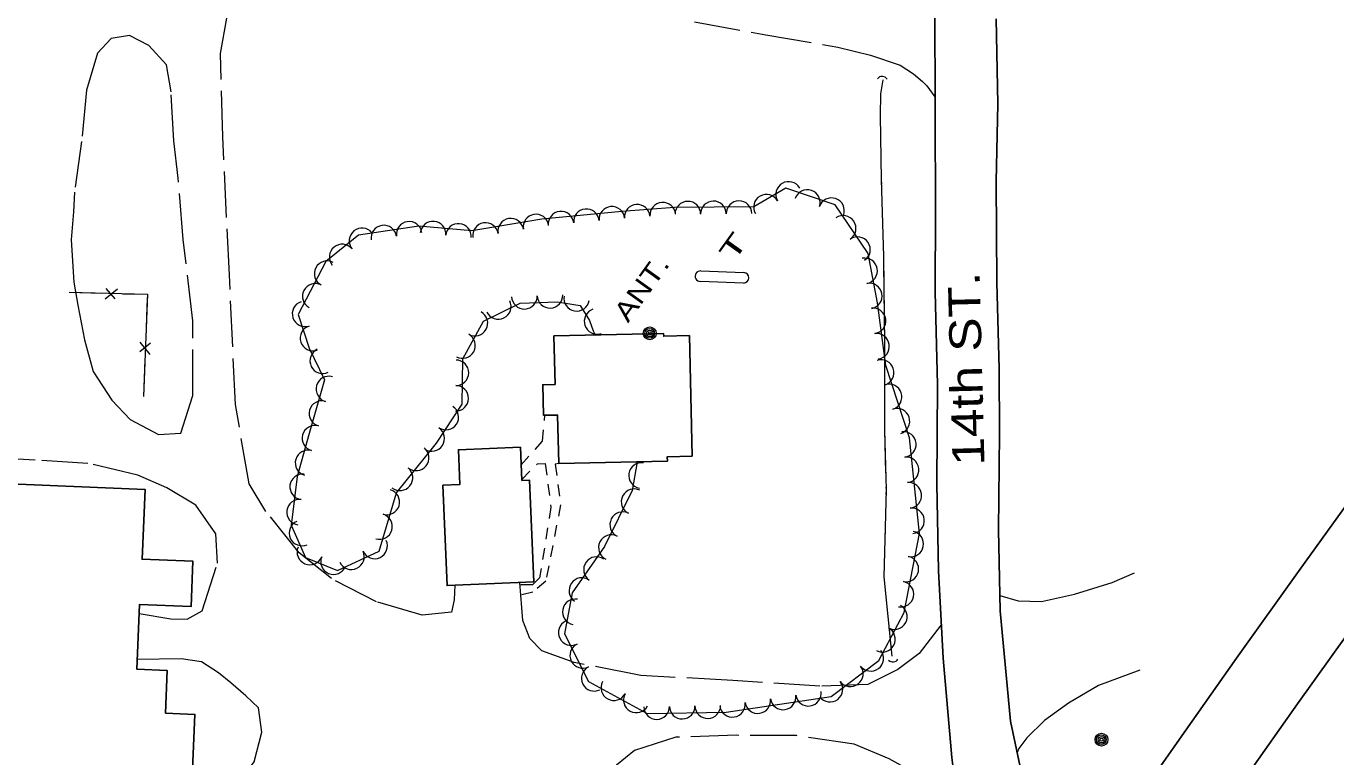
# Model space of a CAD drawing. Extents: x 299311 to 301657, y 49513 to 51866.
# Drawn here: x 300099.8 to 300509.3, y 50383.5 to 50612.1 of the extents above; entities that cross this region are included whole.
import ezdxf

# ---------------------------------------------------------------- set-up
doc = ezdxf.new("R2010")
doc.units = 0
doc.header["$LTSCALE"] = 2.4
doc.linetypes.add('LONG_DASHED', pattern=[7.5, 6, -1.5])
doc.linetypes.add('SHORT_DASHED', pattern=[2.7, 1.5, -1.2])
for name, color, linetype, lineweight in [('11', 7, 'Continuous', 25), ('12', 7, 'Continuous', 25), ('14', 7, 'Continuous', 13), ('15', 7, 'Continuous', 13), ('17', 7, 'LONG_DASHED', 13), ('18', 7, 'Continuous', 13), ('19', 7, 'Continuous', 13)]:
    doc.layers.add(name, color=color, linetype=linetype, lineweight=lineweight)

msp = doc.modelspace()

# ---------------------------------------------------------------- linework, layer by layer
at = {"layer": '11'}
for points in [[(300449.171, 50372.95), (300462.402, 50391.823), (300478.238, 50414.348), (300497.847, 50441.838), (300516.893, 50468.271), (300538.883, 50498.768), (300558.362, 50525.367), (300577.633, 50552.405), (300598.2, 50580.809), (300618.37, 50608.824), (300640.297, 50638.797)], [(300287.176, 50107.164), (300311.291, 50140.598), (300331.977, 50169.98), (300349.427, 50194.729), (300366.089, 50218.225), (300384.892, 50244.576), (300409.609, 50278.747), (300427.494, 50303.203), (300456.56, 50343.148), (300479.329, 50374.693), (300497.325, 50400.091), (300518.311, 50429.548), (300539.854, 50459.658), (300560.519, 50488.121), (300581.893, 50517.65), (300601.128, 50544.137), (300623.029, 50574.5), (300642.077, 50601.015), (300659.645, 50625.084)], [(300269.259, 50122.088), (300283.213, 50142.149), (300299.569, 50164.511), (300317.787, 50189.652), (300334.031, 50212.576), (300349.003, 50233.575), (300364.401, 50254.769), (300378.702, 50274.374), (300384.509, 50284.011), (300388.686, 50295.607), (300391.506, 50308.722), (300393.874, 50322.709), (300394.896, 50338.981), (300392.037, 50360.801), (300389.239, 50383.352), (300386.478, 50414.413), (300385.011, 50441.691), (300384.56, 50468.923), (300384.731, 50500.04), (300383.99, 50528.88), (300384.149, 50554.459), (300383.961, 50584.641), (300383.895, 50619.722)], [(300449.171, 50372.95), (300442.828, 50363.946), (300438.55, 50359.732), (300433.231, 50358.033), (300428.416, 50357.856), (300424.537, 50358.691), (300421.532, 50360.789), (300417.686, 50364.881), (300414.413, 50370.655), (300410.92, 50378.945), (300407.555, 50394.652), (300404.294, 50429.226), (300403.819, 50454.543), (300404.115, 50484.571), (300403.976, 50504.923), (300403.289, 50531.909), (300403.127, 50563.445), (300403.577, 50587.789), (300403.079, 50614.351)]]:
    msp.add_lwpolyline(points, dxfattribs=at)
at = {"layer": '12', "lineweight": 13}
for p, q in [((300324.092, 50531.73), (300310.602, 50532.209)), ((300310.717, 50535.507), (300324.21, 50535.029))]:
    msp.add_line(p, q, dxfattribs=at)
at = {"layer": '12'}
for points in [[(300266.299, 50475.267), (300300.277, 50476.021), (300300.246, 50477.416), (300308.024, 50477.589), (300307.188, 50515.281), (300299.121, 50515.102), (300299.102, 50515.943), (300264.806, 50515.181), (300265.142, 50500.013), (300261.333, 50499.929), (300261.545, 50490.353), (300265.962, 50490.451)], [(300258.474, 50438.236), (300257.154, 50470.104), (300254.774, 50470.005), (300254.344, 50480.389), (300234.944, 50479.585), (300235.394, 50468.713), (300230.076, 50468.493), (300231.375, 50437.114)], [(300075.204, 50355.583), (300150.684, 50352.453), (300152.523, 50396.811), (300143.36, 50397.191), (300143.912, 50410.516), (300134.414, 50410.91), (300135.256, 50431.215), (300151.36, 50430.548), (300151.947, 50444.691), (300136.039, 50445.35), (300136.945, 50467.2), (300079.901, 50469.565), (300077.032, 50400.381), (300077.062, 50400.38)]]:
    msp.add_lwpolyline(points, close=True, dxfattribs=at)
at = {"layer": '12', "lineweight": 13}
for centre, start, end in [((300310.603, 50533.86), 85.99939, 269.95747), ((300324.089, 50533.383), 270.09132, 85.83083)]:
    msp.add_arc(centre, 1.651, start, end, dxfattribs=at)
at = {"layer": '14'}
for centre, radius in [((300294.766, 50515.983), 2.018), ((300294.754, 50515.988), 1.518), ((300294.79, 50515.97), 1.008), ((300294.784, 50515.979), 0.502), ((300436.01, 50388.899), 2.018), ((300435.998, 50388.904), 1.518), ((300436.034, 50388.886), 1.008), ((300436.028, 50388.895), 0.502)]:
    msp.add_circle(centre, radius, dxfattribs=at)
at = {"layer": '15'}
for p, q in [((300113.25, 50528.829), (300123.34, 50528.571)), ((300124.47, 50526.779), (300128.32, 50529.965)), ((300124.726, 50530.057), (300127.477, 50526.771)), ((300137.551, 50524.42), (300137.169, 50514.334)), ((300138.637, 50512.929), (300135.318, 50510.219)), ((300135.363, 50513.226), (300138.501, 50509.337)), ((300136.916, 50507.667), (300136.481, 50496.2))]:
    msp.add_line(p, q, dxfattribs=at)
for points in [[(300113.25, 50528.829), (300137.695, 50528.204), (300136.481, 50496.2)], [(300130.009, 50528.401), (300137.695, 50528.204), (300137.551, 50524.42)]]:
    msp.add_lwpolyline(points, dxfattribs=at)
for centre, radius, start, end in [((300367.416, 50594.42), 1.925, 34.36643, 140.606), ((300370.801, 50415.026), 1.831, 223.01229, 329.25186)]:
    msp.add_arc(centre, radius, start, end, dxfattribs=at)
at = {"layer": '17'}
for points in [[(300233.861, 50437.217), (300233.62, 50432.589), (300232.743, 50428.76), (300223.603, 50427.836), (300209.35, 50431.988), (300195.203, 50439.297), (300185.173, 50447.328), (300174.753, 50460.277), (300169.525, 50468.915), (300165.206, 50493.763), (300163.339, 50534.29), (300161.242, 50577.44), (300160.542, 50603.478), (300162.516, 50614.622)], [(300308.719, 50613.396), (300331.014, 50609.391), (300353.628, 50605.541), (300363.833, 50602.97), (300373.029, 50599.854), (300377.242, 50597.133), (300380.062, 50594.745), (300381.456, 50593.43), (300383.951, 50589.98)], [(300145.986, 50576.187), (300145.101, 50591.491), (300143.702, 50599.995), (300138.115, 50606.053), (300132.052, 50609.121), (300126.366, 50608.209), (300122.093, 50603.637), (300118.668, 50592.007), (300117.11, 50575.995), (300114.845, 50560.107), (300114.531, 50554.007), (300113.822, 50545.239)], [(300113.822, 50545.239), (300114.736, 50532.009), (300115.893, 50524.788), (300117.989, 50513.965), (300120.773, 50504.016), (300126.518, 50495.13), (300132.328, 50489.036), (300141.163, 50484.387), (300148.154, 50484.758), (300151.871, 50496.512), (300151.947, 50519.882), (300148.894, 50545.34), (300147.292, 50564.498), (300145.986, 50576.187)], [(300135.136, 50428.313), (300145.034, 50426.682), (300150.079, 50426.555), (300154.774, 50429.152), (300159.582, 50444.074), (300159.043, 50453.242), (300152.867, 50462.22), (300143.726, 50467.655), (300134.75, 50471.645), (300119.03, 50475.313), (300102.604, 50476.359), (300091.393, 50476.983), (300082.47, 50476.033), (300078.91, 50474.449), (300076.048, 50470.85), (300075.066, 50467.222), (300075.651, 50464.031), (300078.495, 50463.4), (300079.637, 50463.196)], [(300385.916, 50424.856), (300379.001, 50415.859), (300372.351, 50410.852), (300362.931, 50406.179), (300347.979, 50405.638), (300320.734, 50407.37), (300291.939, 50409.01), (300271.098, 50413.044), (300261.068, 50416.67), (300257.319, 50420.522), (300255.053, 50426.18), (300254.157, 50438.057)], [(300404.204, 50434.011), (300409.985, 50432.355), (300417.247, 50432.144), (300427.556, 50434.444), (300439.39, 50438.089), (300446.338, 50441.131)], [(300151.534, 50372.964), (300159.803, 50373.485), (300167.09, 50376.697), (300171.057, 50382.007), (300173.442, 50391.22), (300172.447, 50398.873), (300168.434, 50402.595), (300163.742, 50406.624), (300159.944, 50409.807), (300154.601, 50413.244), (300148.266, 50414.175), (300134.542, 50413.988)], [(300448.004, 50410.62), (300435.123, 50405.811), (300425.655, 50400.299), (300418.176, 50394.852), (300412.64, 50389.523), (300410.194, 50386.171), (300409.656, 50384.843)], [(300391.448, 50365.545), (300385.301, 50372.924), (300377.884, 50378.354), (300369.581, 50382.944), (300358.66, 50387.471), (300340.613, 50390.152), (300322.022, 50390.254), (300302.879, 50389.645), (300289.98, 50385.488), (300284.399, 50380.961), (300281.379, 50372.308), (300281.527, 50361.869), (300283.227, 50347.108), (300285.594, 50315.666), (300289.573, 50290.615), (300292.477, 50276.643), (300293.16, 50263.815), (300290.486, 50246.073), (300288.337, 50240.446)]]:
    msp.add_lwpolyline(points, dxfattribs=at)
at = {"layer": '17', "linetype": 'SHORT_DASHED'}
for points in [[(300254.573, 50474.865), (300261.276, 50482.271), (300261.962, 50490.362)], [(300254.762, 50470.286), (300259.673, 50475.222), (300262.098, 50475.241), (300263.842, 50461.608), (300260.324, 50439.474), (300258.07, 50437.364), (300254.212, 50437.325)], [(300266.368, 50475.269), (300265.184, 50475.1), (300266.884, 50462.371), (300262.288, 50438.522), (300258.256, 50435.018), (300254.451, 50434.157)]]:
    msp.add_lwpolyline(points, dxfattribs=at)
at = {"layer": '18'}
msp.add_lwpolyline([(300290.785, 50475.817), (300289.273, 50466.824), (300280.578, 50449.288), (300270.473, 50434.801), (300268.06, 50422.047), (300275.582, 50407.057), (300294, 50397.095), (300318.655, 50397.543), (300351.493, 50402.349), (300366.378, 50413.629), (300374.302, 50428.651), (300379.161, 50453.365), (300375.936, 50483.324), (300368.611, 50505.9), (300365.937, 50525.54), (300363.064, 50540.965), (300352.793, 50556.158), (300337.346, 50561.364), (300327.282, 50555.572), (300302.465, 50555.339), (300286.018, 50554.067), (300261.043, 50551.67), (300239.158, 50548.022), (300222.601, 50549.539), (300203.664, 50546.715), (300193.527, 50538.447), (300184.838, 50521.926), (300188.314, 50511.322), (300193.069, 50501.443), (300188.319, 50484.644), (300184.532, 50471.164), (300182.62, 50456.014), (300187.15, 50445.9), (300197.153, 50441.784), (300210.17, 50447.868), (300215.588, 50466.149), (300228.13, 50481.629), (300236.159, 50493.87), (300236.288, 50507.974), (300242.834, 50519.799), (300254.244, 50525.457), (300265.866, 50525.897), (300272.98, 50524.661), (300275.962, 50520.062), (300277.078, 50516.79), (300277.795, 50515.343)], dxfattribs=at)
for centre, start, end in [((300338.184, 50559.431), 29.92881, 209.91349), ((300344.033, 50556.901), 341.38264, 161.36732), ((300290.854, 50552.341), 4.43008, 184.41475), ((300298.83, 50552.958), 4.43008, 184.41475), ((300306.677, 50553.285), 0.54558, 180.53026), ((300314.676, 50553.36), 0.54558, 180.53026), ((300322.676, 50553.435), 0.54558, 180.53026), ((300331.251, 50555.44), 29.92881, 209.91349), ((300351.614, 50554.346), 341.38264, 161.36732), ((300259.196, 50549.239), 9.47126, 189.45594), ((300266.995, 50550.138), 5.48989, 185.47457), ((300274.958, 50550.902), 5.48989, 185.47457), ((300282.922, 50551.666), 5.48989, 185.47457), ((300355.237, 50548.804), 304.06773, 124.05241), ((300204.785, 50544.927), 39.20924, 219.19392), ((300211.627, 50545.786), 8.48945, 188.47413), ((300219.539, 50546.966), 8.48945, 188.47413), ((300226.983, 50547.035), 354.77267, 174.75735), ((300234.95, 50546.305), 354.77267, 174.75735), ((300243.414, 50546.609), 9.47126, 189.45594), ((300251.305, 50547.924), 9.47126, 189.45594), ((300359.718, 50542.177), 304.06773, 124.05241), ((300198.586, 50539.871), 39.20924, 219.19392), ((300193.9, 50534.658), 62.26613, 242.25081), ((300361.943, 50535.546), 280.55845, 100.54313), ((300363.408, 50527.682), 280.55845, 100.54313), ((300190.176, 50527.578), 62.26613, 242.25081), ((300255.569, 50527.602), 182.1758, 2.16048), ((300263.563, 50527.905), 182.1758, 2.16048), ((300271.914, 50526.971), 170.15137, 350.13605), ((300186.987, 50522.091), 108.15685, 288.14153), ((300247.405, 50524.403), 206.38359, 26.36827), ((300278.29, 50519.723), 108.84093, 288.82561), ((300364.595, 50519.876), 277.76085, 97.74553), ((300240.102, 50519.186), 241.03994, 61.02461), ((300189.479, 50514.489), 108.15685, 288.14153), ((300236.227, 50512.187), 241.03994, 61.02461), ((300365.674, 50511.949), 277.76085, 97.74553), ((300192.522, 50507.406), 115.71029, 295.69497), ((300234.155, 50503.65), 269.48363, 89.46831), ((300367.116, 50503.722), 287.98381, 107.96849), ((300194.434, 50498.574), 74.21915, 254.20383), ((300234.081, 50495.651), 269.48363, 89.46831), ((300369.585, 50496.113), 287.98381, 107.96849), ((300192.257, 50490.876), 74.21915, 254.20383), ((300230.987, 50489.802), 236.74638, 56.73105), ((300372.054, 50488.504), 287.98381, 107.96849), ((300190.083, 50483.181), 74.31577, 254.30044), ((300226.599, 50483.113), 236.74638, 56.73105), ((300374.055, 50481.236), 276.15173, 96.13641), ((300187.919, 50475.479), 74.31577, 254.30044), ((300221.72, 50477.043), 230.99304, 50.97772), ((300292.187, 50471.525), 80.46374, 260.44842), ((300374.911, 50473.282), 276.15173, 96.13641), ((300186.242, 50467.995), 82.8147, 262.79937), ((300216.683, 50470.827), 230.99304, 50.97772), ((300212.536, 50463.22), 253.49924, 73.48392), ((300289.869, 50463.313), 63.63374, 243.61842), ((300375.767, 50465.328), 276.15173, 96.13641), ((300185.241, 50460.058), 82.8147, 262.79937), ((300210.263, 50455.55), 253.49924, 73.48392), ((300286.315, 50456.145), 63.63374, 243.61842), ((300376.624, 50457.374), 276.15173, 96.13641), ((300186.027, 50453.53), 114.13498, 294.11966), ((300376.385, 50450.096), 258.88466, 78.86933), ((300208.732, 50449.507), 205.05852, 25.0432), ((300282.761, 50448.978), 63.63374, 243.61842), ((300188.481, 50447.617), 157.64164, 337.62632), ((300195.879, 50444.572), 157.64164, 337.62632), ((300201.485, 50446.12), 205.05852, 25.0432), ((300278.115, 50442.097), 55.11104, 235.09572), ((300374.841, 50442.247), 258.88466, 78.86933), ((300273.538, 50435.535), 55.11104, 235.09572), ((300373.298, 50434.397), 258.88466, 78.86933), ((300271.481, 50428.866), 79.29419, 259.27886), ((300371.258, 50427.368), 242.19633, 62.18101), ((300270.229, 50422.393), 116.65521, 296.63989), ((300367.525, 50420.292), 242.19633, 62.18101), ((300273.817, 50415.242), 116.65521, 296.63989), ((300363.861, 50414.349), 217.16287, 37.14755), ((300277.405, 50408.092), 116.65521, 296.63989), ((300357.485, 50409.517), 217.16287, 37.14755), ((300283.52, 50405.144), 151.59942, 331.5841), ((300351.109, 50404.685), 217.16287, 37.14755), ((300290.557, 50401.338), 151.59942, 331.5841), ((300328.536, 50401.105), 188.33406, 8.31874), ((300336.452, 50402.264), 188.33406, 8.31874), ((300344.368, 50403.422), 188.33406, 8.31874), ((300296.914, 50399.242), 181.04866, 1.03333), ((300304.913, 50399.387), 181.04866, 1.03333), ((300312.911, 50399.533), 181.04866, 1.03333), ((300320.621, 50399.947), 188.33406, 8.31874)]:
    msp.add_arc(centre, 4, start, end, dxfattribs=at)
at = {"layer": '19'}
for p, q in [((300367.484, 50555.871), (300367.417, 50558.127)), ((300367.686, 50549.103), (300367.619, 50551.359)), ((300367.889, 50542.335), (300367.821, 50544.591)), ((300368.553, 50458.87), (300368.611, 50461.125)), ((300368.381, 50452.107), (300368.439, 50454.362))]:
    msp.add_line(p, q, dxfattribs=at)
for points in [[(300370.538, 50415.014), (300368.069, 50439.833), (300368.761, 50467.027), (300368.314, 50485.783), (300368.298, 50512.572), (300367.958, 50540.007), (300367.238, 50564.126), (300366.956, 50584.053), (300367.057, 50590.911), (300367.798, 50595.279)], [(300367.282, 50562.639), (300367.238, 50564.126), (300366.956, 50584.053), (300367.057, 50590.911), (300367.798, 50595.279)], [(300368.302, 50505.097), (300368.298, 50512.572), (300367.985, 50537.822)], [(300368.633, 50472.395), (300368.314, 50485.783), (300368.302, 50505.097)], [(300368.726, 50465.633), (300368.761, 50467.027), (300368.74, 50467.887)], [(300370.538, 50415.014), (300368.069, 50439.833), (300368.267, 50447.599)]]:
    msp.add_lwpolyline(points, dxfattribs=at)

# ---------------------------------------------------------------- texts
at = {"layer": '11', "width": 1.2}
msp.add_text('14th ST.', height=10, rotation=91.458, dxfattribs=at).set_placement((300399.45, 50474.686))
at = {"layer": '12', "width": 1.7}
msp.add_text('T', height=6, rotation=54.366, dxfattribs=at).set_placement((300320.932, 50537.984))
at = {"layer": '14', "width": 1.25}
msp.add_text('ANT.', height=6, rotation=54.366, dxfattribs=at).set_placement((300287.968, 50519.062))

doc.saveas('drawing.dxf')
